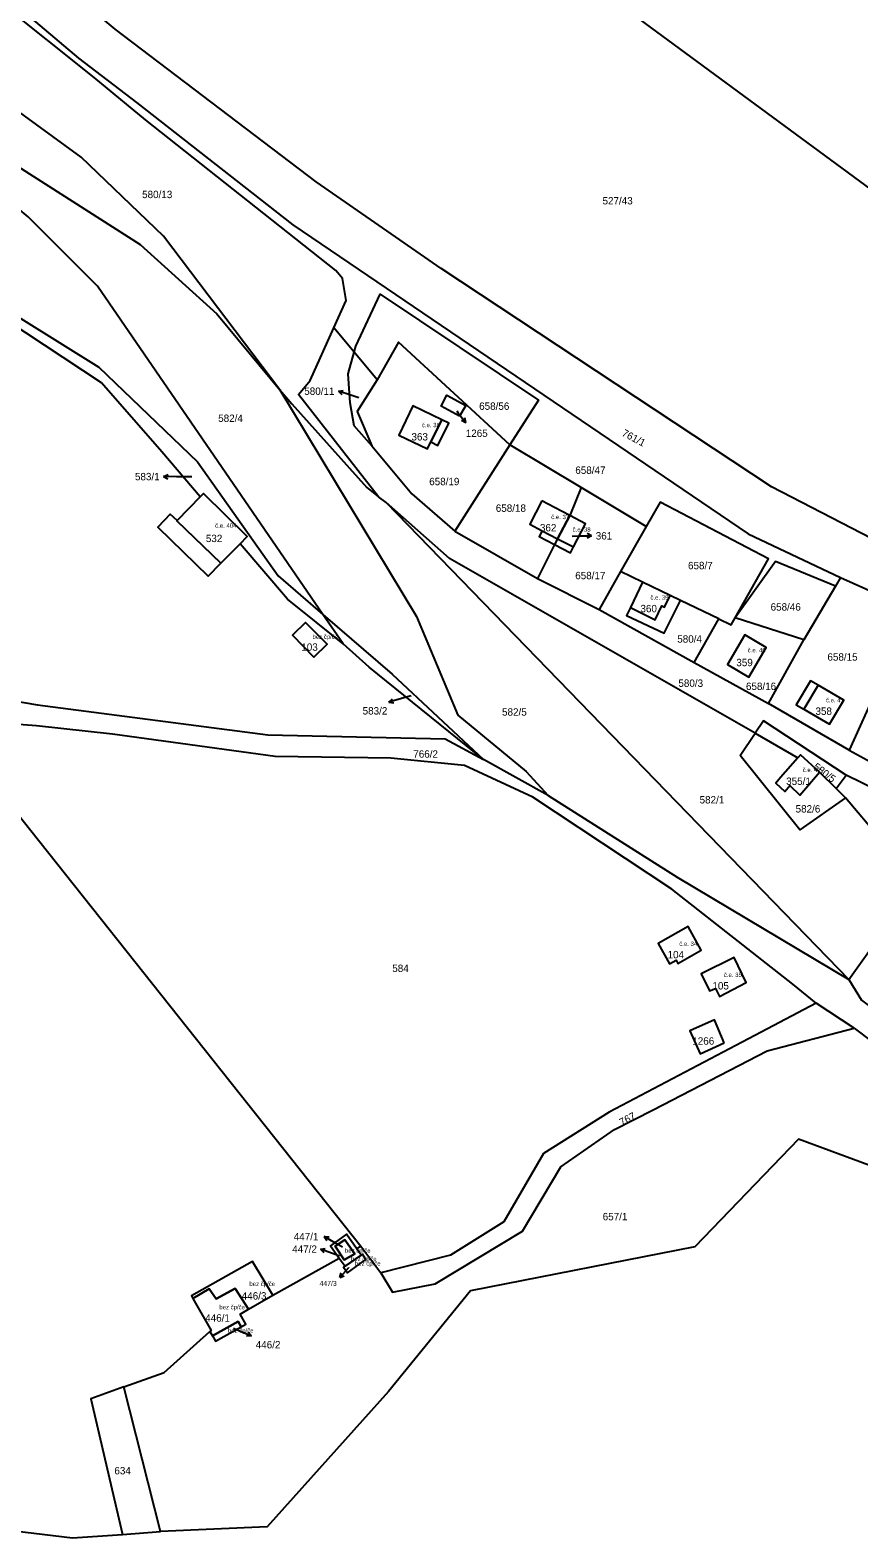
# Model space of a CAD drawing. Extents: x -887272 to -880188, y -1026687 to -1021896.
# Drawn here: x -884099.9 to -883908.9, y -1024224.8 to -1023877.6 of the extents above; entities that cross this region are included whole.
import ezdxf

# ---------------------------------------------------------------- set-up
doc = ezdxf.new("R2010")
doc.units = 0
for name, color, linetype in [('Definiční body', 7, 'Continuous'), ('Hranice parcel', 7, 'Continuous'), ('Parcelní čísla', 7, 'Continuous'), ('Polygon budovy', 7, 'Continuous'), ('Pop  PČ popisy', 7, 'Continuous'), ('Vnitřní kresba', 7, 'Continuous')]:
    doc.layers.add(name, color=color, linetype=linetype)

msp = doc.modelspace()

# ---------------------------------------------------------------- linework, layer by layer
at = {"layer": 'Hranice parcel'}
for p, q in [((-884025.18, -1023951.76), (-884029.85, -1023946.15)), ((-884019.89, -1023958.13), (-884025.18, -1023951.76)), ((-884042.31, -1023960.46), (-884039.58, -1023963.62)), ((-884011.69, -1023964.11), (-884014.91, -1023970.83)), ((-883989.29, -1023973.09), (-884001.97, -1023992.99)), ((-883972.86, -1023982.93), (-883989.29, -1023973.09)), ((-883972.86, -1023982.93), (-883975.49, -1023989.4)), ((-883957.89, -1023991.9), (-883972.86, -1023982.93)), ((-884017.85, -1023986.37), (-884019.55, -1023985.04)), ((-884017.85, -1023986.37), (-883911.25, -1024096.23)), ((-884001.97, -1023992.99), (-883982.95, -1024003.91)), ((-883957.89, -1023991.9), (-883963.8, -1024002.3)), ((-883979, -1023996.03), (-883982.95, -1024003.91)), ((-883982.95, -1024003.91), (-883968.75, -1024010.99)), ((-883963.8, -1024002.3), (-883968.75, -1024010.99)), ((-883958.76, -1024004.73), (-883963.8, -1024002.3)), ((-883913.13, -1024003.65), (-883914.3, -1024005.63)), ((-883914.3, -1024005.63), (-883921.56, -1024018.02)), ((-883941.19, -1024013.18), (-883949.97, -1024008.96)), ((-884027.71, -1024018.94), (-884032.38, -1024012.15)), ((-883968.75, -1024010.99), (-883946.83, -1024023.21)), ((-883946.83, -1024023.21), (-883941.19, -1024013.18)), ((-883921.56, -1024018.02), (-883937.39, -1024012.91)), ((-883929.72, -1024032.63), (-883921.56, -1024018.02)), ((-883946.83, -1024023.21), (-883929.72, -1024032.63)), ((-883904.58, -1024028.99), (-883911.13, -1024043.4)), ((-883911.13, -1024043.4), (-883929.72, -1024032.63)), ((-884120.19, -1024036.18), (-884023.67, -1024157.61)), ((-883936.29, -1024044.64), (-883932.83, -1024039.52)), ((-883932.83, -1024039.52), (-883922.95, -1024045.18)), ((-883980.51, -1024053.85), (-883995.38, -1024045.56)), ((-883911.13, -1024043.4), (-883899.81, -1024049.6)), ((-883917.94, -1024048.45), (-883914.16, -1024052.25)), ((-883914.16, -1024052.25), (-883911.85, -1024049.13)), ((-883898.73, -1024055.6), (-883911.85, -1024049.13)), ((-883912, -1024054.42), (-883914.16, -1024052.25)), ((-883980.51, -1024053.85), (-883950.8, -1024072.68)), ((-883904.07, -1024063.74), (-883912, -1024054.42)), ((-883950.8, -1024072.68), (-883911.25, -1024096.23)), ((-883911.25, -1024096.23), (-883895, -1024073.52)), ((-883909.98, -1024107.42), (-883918.72, -1024101.7)), ((-884027.29, -1024162.27), (-884023.6, -1024159.68)), ((-884024.65, -1024158.16), (-884023.67, -1024157.61)), ((-884023.6, -1024159.68), (-884024.65, -1024158.16)), ((-884023.67, -1024157.61), (-884019.06, -1024163.76)), ((-884043.9, -1024168.9), (-884028.63, -1024160.38)), ((-884028.63, -1024160.38), (-884027.29, -1024162.27)), ((-884049.54, -1024172.16), (-884043.9, -1024168.9)), ((-884058.46, -1024177.26), (-884057.87, -1024178.3)), ((-884069.78, -1024223.36), (-884078.26, -1024190.02)), ((-884078.6, -1024224), (-884069.78, -1024223.36))]:
    msp.add_line(p, q, dxfattribs=at)
for points in [[(-883756.5, -1024023.04), (-883767.66, -1024020.24), (-883797.06, -1024014.34), (-883842.62, -1024005.56), (-883874.8, -1024002.84), (-883906.02, -1023994.68), (-883929.04, -1023982.78), (-884005.12, -1023932.5), (-884033.98, -1023912.56), (-884080.28, -1023877.34), (-884136.58, -1023830.48), (-884162.3, -1023804.42), (-884180.14, -1023781.6), (-884204.86, -1023736.02), (-884224.62, -1023704.92), (-884247.24, -1023674.52), (-884253.66, -1023666.34), (-884254.22, -1023665.64)], [(-884128.87, -1023850.09), (-884088.74, -1023884.02), (-884075.38, -1023894.24), (-884039.32, -1023922.42), (-883934.44, -1023993.58), (-883913.13, -1024003.65)], [(-884042.31, -1023960.46), (-884069.15, -1023925.03), (-884088.08, -1023906.88), (-884124.51, -1023880.4), (-884129.67, -1023875.3), (-884133.64, -1023867.29), (-884134.98, -1023857.41), (-884133.42, -1023855.44), (-884132.27, -1023853.18), (-884130.36, -1023851.44)], [(-884029.85, -1023946.15), (-884027.02, -1023939.86), (-884027.86, -1023934.82), (-884029.41, -1023932.93), (-884073.28, -1023898.24), (-884085.07, -1023888.47), (-884106.9, -1023871.17), (-884122.73, -1023858.32), (-884130.36, -1023851.44)], [(-883979.65, -1023860.19), (-883882, -1023932), (-883653, -1023925)], [(-884134.64, -1023892.14), (-884120.26, -1023897.78), (-884074.52, -1023926.94), (-884056.83, -1023942.92), (-884042.31, -1023960.46)], [(-884032.38, -1024012.15), (-884084.32, -1023936.55), (-884100.33, -1023920.58), (-884134.64, -1023892.14)], [(-884060.68, -1023985.09), (-884069.54, -1023974.7), (-884083.38, -1023958.84), (-884122.86, -1023932.78), (-884157.22, -1023909.6)], [(-884157.22, -1023909.6), (-884084, -1023955.24), (-884061.26, -1023976.98), (-884042.7, -1024003.23), (-884032.38, -1024012.15)], [(-884025.18, -1023951.76), (-884024.81, -1023950.4), (-884019.24, -1023938.38), (-883982.71, -1023962.83), (-883989.29, -1023973.09)], [(-884019.55, -1023985.04), (-884038.05, -1023961.5), (-884035.31, -1023958.31), (-884029.85, -1023946.15)], [(-884021.14, -1023973.35), (-884025.21, -1023968.69), (-884026.08, -1023963.45), (-884026.55, -1023956.74), (-884025.18, -1023951.76)], [(-883989.29, -1023973.09), (-884014.99, -1023949.47), (-884019.89, -1023958.13)], [(-884019.89, -1023958.13), (-884024.5, -1023965.42), (-884021.14, -1023973.35)], [(-884042.31, -1023960.46), (-884010.85, -1024012.66), (-884001.27, -1024035.34), (-883985.6, -1024048.34), (-883980.51, -1024053.85)], [(-884000.92, -1023966.48), (-884005.13, -1023964.17), (-884003.82, -1023961.66), (-883999.45, -1023964.04), (-884000.92, -1023966.48)], [(-884039.58, -1023963.62), (-884022.28, -1023982.92), (-884019.55, -1023985.04)], [(-884014.91, -1023970.83), (-884008.33, -1023973.99), (-884007.55, -1023972.42), (-884005.95, -1023973.22), (-884003.4, -1023968.09), (-884005.02, -1023967.31), (-884011.69, -1023964.11)], [(-884021.14, -1023973.35), (-884011.88, -1023984.41), (-884001.97, -1023992.99)], [(-884060.68, -1023985.09), (-884065.94, -1023990.48), (-884067.55, -1023989.03), (-884070.44, -1023992.08), (-884058.82, -1024003.33), (-884055.91, -1024000.36), (-884051.49, -1023995.86)], [(-884051.49, -1023995.86), (-884049.83, -1023994.17), (-884059.91, -1023984.31), (-884060.68, -1023985.09)], [(-883932.83, -1024039.52), (-884003.19, -1023999.25), (-884017.85, -1023986.37)], [(-883981.99, -1023985.98), (-883984.7, -1023991.4), (-883981.87, -1023992.87)], [(-883975.49, -1023989.4), (-883979.06, -1023987.52), (-883981.99, -1023985.98)], [(-883937.39, -1024012.91), (-883929.74, -1023999.31), (-883954.68, -1023986.26), (-883957.89, -1023991.9)], [(-883975.49, -1023989.4), (-883978.31, -1023994.72), (-883979, -1023996.03)], [(-883979, -1023996.03), (-883975.36, -1023997.94), (-883974.68, -1023996.61), (-883971.93, -1023991.27), (-883975.49, -1023989.4)], [(-883981.87, -1023992.87), (-883982.55, -1023994.17), (-883979, -1023996.03)], [(-884027.71, -1024018.94), (-884040.58, -1024008.66), (-884051.49, -1023995.86)], [(-883914.3, -1024005.63), (-883928.14, -1023999.97), (-883937.39, -1024012.91)], [(-883913.13, -1024003.65), (-883904.38, -1024007.55), (-883899.62, -1024008.57)], [(-883958.76, -1024004.73), (-883961.55, -1024010.54), (-883962.46, -1024012.43), (-883953.74, -1024016.44), (-883949.97, -1024008.96)], [(-883949.97, -1024008.96), (-883952.36, -1024007.81), (-883958.76, -1024004.73)], [(-884039.41, -1024016.96), (-884034.45, -1024022), (-884031.43, -1024019.01), (-884036.38, -1024013.97), (-884039.41, -1024016.96)], [(-884032.38, -1024012.15), (-884016.42, -1024025.94), (-883995.38, -1024045.56)], [(-883941.19, -1024013.18), (-883938.35, -1024014.55), (-883937.39, -1024012.91)], [(-883935.21, -1024016.88), (-883939.2, -1024023.69), (-883934.27, -1024026.57), (-883930.29, -1024019.76), (-883935.21, -1024016.88)], [(-883995.38, -1024045.56), (-884021.72, -1024024.3), (-884027.71, -1024018.94)], [(-883918.3, -1024028.44), (-883920.05, -1024027.41), (-883923.36, -1024032.97), (-883921.6, -1024033.98), (-883915.64, -1024037.39), (-883912.38, -1024031.92), (-883918.3, -1024028.44)], [(-884123.06, -1024028.78), (-884098.18, -1024033), (-884045.1, -1024039.86), (-884004.26, -1024040.76), (-883995.38, -1024045.56)], [(-883918.72, -1024101.7), (-883924.14, -1024097.32), (-883952.02, -1024075.4), (-883984.02, -1024054.24), (-883999.74, -1024046.96), (-884016.72, -1024045.28), (-884043.42, -1024044.88), (-884080.84, -1024039.76), (-884098.38, -1024037.82), (-884120.19, -1024036.18)], [(-883911.85, -1024049.13), (-883930.9, -1024036.66), (-883932.83, -1024039.52)], [(-883912, -1024054.42), (-883922.51, -1024061.72), (-883936.29, -1024044.64)], [(-883922.95, -1024045.18), (-883926.93, -1024049.72), (-883928.07, -1024051.03), (-883925.94, -1024052.89), (-883924.8, -1024051.58), (-883922.51, -1024053.75), (-883917.94, -1024048.45)], [(-883917.94, -1024048.45), (-883922.36, -1024044.5), (-883922.95, -1024045.18)], [(-883945.27, -1024089.47), (-883948.2, -1024084.04), (-883955.18, -1024087.9), (-883952.57, -1024092.61), (-883951.04, -1024091.78), (-883950.61, -1024092.57), (-883945.27, -1024089.47)], [(-883941.94, -1024098.28), (-883941.02, -1024100.12), (-883934.9, -1024096.9), (-883937.64, -1024091.14), (-883945.24, -1024094.94), (-883943.34, -1024098.86), (-883941.94, -1024098.28)], [(-883911.25, -1024096.23), (-883908.31, -1024100.98), (-883902.86, -1024105.05)], [(-883918.72, -1024101.7), (-883931.44, -1024108.36), (-883966.42, -1024126.78), (-883981.56, -1024136.28), (-883990.7, -1024152.04), (-884002.96, -1024159.72), (-884019.06, -1024163.76)], [(-884019.06, -1024163.76), (-884016.34, -1024168.22), (-884006.56, -1024166.28), (-883986.4, -1024154.2), (-883977.56, -1024139.36), (-883965.2, -1024130.78), (-883956.28, -1024126.24), (-883930.04, -1024112.68), (-883909.98, -1024107.42)], [(-883939.92, -1024110.82), (-883942.16, -1024105.54), (-883947.82, -1024108.04), (-883945.46, -1024113.34), (-883939.92, -1024110.82)], [(-883909.98, -1024107.42), (-883905.62, -1024110.7), (-883897.3, -1024115.95)], [(-883855.91, -1024158.43), (-883859.24, -1024156.52), (-883860.34, -1024160.64), (-883875.1, -1024156.8), (-883873.62, -1024151.2), (-883922.82, -1024133), (-883946.68, -1024157.76), (-883998.42, -1024167.88), (-884017.26, -1024191.06), (-884045.27, -1024222.29), (-884069.78, -1024223.36)], [(-884024.65, -1024158.16), (-884026.93, -1024154.88), (-884030.62, -1024157.55), (-884028.63, -1024160.38)], [(-884027.36, -1024156.14), (-884029.58, -1024157.62), (-884027.48, -1024160.78), (-884025.04, -1024159.4), (-884027.36, -1024156.14)], [(-884027.29, -1024162.27), (-884027.62, -1024162.5), (-884026.74, -1024163.8), (-884022.48, -1024160.71), (-884023.31, -1024159.48), (-884023.6, -1024159.68)], [(-884263.42, -1024162.52), (-884211.46, -1024160.89), (-884176.88, -1024188.36), (-884125.84, -1024220.46), (-884090.08, -1024224.8), (-884078.6, -1024224)], [(-884043.9, -1024168.9), (-884048.59, -1024161.14), (-884062.67, -1024169.09), (-884062.34, -1024169.66)], [(-884049.54, -1024172.16), (-884052.64, -1024167.36), (-884057, -1024169.76), (-884058.6, -1024167.46), (-884062.34, -1024169.66)], [(-884062.34, -1024169.66), (-884058.11, -1024177.06), (-884058.46, -1024177.26)], [(-884051.21, -1024176.18), (-884050.18, -1024175.6), (-884051.46, -1024173.28), (-884049.54, -1024172.16)], [(-884078.26, -1024190.02), (-884069, -1024186.76), (-884058.46, -1024177.26)], [(-884057.87, -1024178.3), (-884051.94, -1024174.94), (-884051.21, -1024176.18)], [(-884057.87, -1024178.3), (-884057.14, -1024179.54), (-884051.21, -1024176.18)], [(-884078.26, -1024190.02), (-884085.9, -1024192.78), (-884078.6, -1024224)]]:
    msp.add_lwpolyline(points, dxfattribs=at)
at = {"layer": 'Polygon budovy'}
for points in [[(-884008.33, -1023973.99), (-884007.55, -1023972.42), (-884005.02, -1023967.31), (-884011.69, -1023964.11), (-884014.91, -1023970.83)], [(-884051.49, -1023995.86), (-884049.83, -1023994.17), (-884059.91, -1023984.31), (-884060.68, -1023985.09), (-884065.94, -1023990.48), (-884066.02, -1023990.57), (-884055.91, -1024000.36)], [(-883981.99, -1023985.98), (-883984.7, -1023991.4), (-883981.87, -1023992.87), (-883978.31, -1023994.72), (-883975.49, -1023989.4), (-883979.06, -1023987.52)], [(-883975.49, -1023989.4), (-883978.31, -1023994.72), (-883974.68, -1023996.61), (-883971.93, -1023991.27)], [(-883958.76, -1024004.73), (-883961.55, -1024010.54), (-883955.87, -1024013.38), (-883954.34, -1024010.18), (-883953.66, -1024010.51), (-883952.36, -1024007.81)], [(-884031.43, -1024019.01), (-884036.38, -1024013.97), (-884039.41, -1024016.96), (-884034.45, -1024022)], [(-883930.29, -1024019.76), (-883935.21, -1024016.88), (-883939.2, -1024023.69), (-883934.27, -1024026.57)], [(-883912.38, -1024031.92), (-883918.3, -1024028.44), (-883921.6, -1024033.98), (-883915.64, -1024037.39)], [(-883922.36, -1024044.5), (-883922.95, -1024045.18), (-883926.93, -1024049.72), (-883928.07, -1024051.03), (-883925.94, -1024052.89), (-883924.8, -1024051.58), (-883922.51, -1024053.75), (-883917.94, -1024048.45)], [(-883955.18, -1024087.9), (-883952.57, -1024092.61), (-883951.04, -1024091.78), (-883950.61, -1024092.57), (-883945.27, -1024089.47), (-883948.2, -1024084.04)], [(-883945.24, -1024094.94), (-883943.34, -1024098.86), (-883941.94, -1024098.28), (-883941.02, -1024100.12), (-883934.9, -1024096.9), (-883937.64, -1024091.14)], [(-884027.29, -1024162.27), (-884023.6, -1024159.68), (-884024.65, -1024158.16), (-884026.93, -1024154.88), (-884030.62, -1024157.55), (-884028.63, -1024160.38)], [(-884027.48, -1024160.78), (-884025.04, -1024159.4), (-884027.36, -1024156.14), (-884029.58, -1024157.62)], [(-884029.58, -1024157.62), (-884027.36, -1024156.14), (-884025.04, -1024159.4), (-884027.48, -1024160.78)], [(-884027.29, -1024162.27), (-884027.62, -1024162.5), (-884026.74, -1024163.8), (-884022.48, -1024160.71), (-884023.31, -1024159.48), (-884023.6, -1024159.68)], [(-884052.64, -1024167.36), (-884049.54, -1024172.16), (-884043.9, -1024168.9), (-884048.59, -1024161.14), (-884062.67, -1024169.09), (-884062.34, -1024169.66), (-884058.6, -1024167.46), (-884057, -1024169.76)], [(-884049.54, -1024172.16), (-884052.64, -1024167.36), (-884057, -1024169.76), (-884058.6, -1024167.46), (-884062.34, -1024169.66), (-884058.11, -1024177.06), (-884058.46, -1024177.26), (-884057.87, -1024178.3), (-884051.94, -1024174.94), (-884051.21, -1024176.18), (-884050.18, -1024175.6), (-884051.46, -1024173.28)], [(-884057.87, -1024178.3), (-884057.14, -1024179.54), (-884051.21, -1024176.18), (-884051.94, -1024174.94)]]:
    msp.add_lwpolyline(points, close=True, dxfattribs=at)
at = {"layer": 'Pop  PČ popisy'}
for p, q in [((-884028.84, -1023960.74), (-884027.74, -1023960.58)), ((-884025.99, -1023961.67), (-884028.84, -1023960.74)), ((-884028.84, -1023960.74), (-884028.05, -1023961.53)), ((-884024.1, -1023962.29), (-884025.99, -1023961.67)), ((-884001.51, -1023965.3), (-884001.28, -1023965.61)), ((-884001.28, -1023965.61), (-883999.47, -1023968.01)), ((-883999.47, -1023968.01), (-884000.48, -1023967.51)), ((-883999.47, -1023968.01), (-883999.68, -1023966.91)), ((-884069.09, -1023980.39), (-884068.08, -1023979.9)), ((-884066.09, -1023980.44), (-884069.09, -1023980.39)), ((-884069.09, -1023980.39), (-884068.1, -1023980.91)), ((-884062.57, -1023980.48), (-884066.09, -1023980.44)), ((-883970.53, -1023994.03), (-883971.54, -1023993.54)), ((-883974.99, -1023994.1), (-883973.53, -1023994.08)), ((-883973.53, -1023994.08), (-883970.53, -1023994.03)), ((-883970.53, -1023994.03), (-883971.52, -1023994.55)), ((-884014.28, -1024031.51), (-884017.17, -1024032.34)), ((-884017.17, -1024032.34), (-884016.34, -1024031.58)), ((-884012.07, -1024030.86), (-884014.28, -1024031.51)), ((-884017.17, -1024032.34), (-884016.06, -1024032.54)), ((-884029.49, -1024156.92), (-884032.09, -1024155.42)), ((-884032.09, -1024155.42), (-884030.97, -1024155.49)), ((-884032.09, -1024155.42), (-884031.47, -1024156.35)), ((-884032.98, -1024158.3), (-884031.87, -1024158.18)), ((-884030.16, -1024159.33), (-884032.98, -1024158.3)), ((-884032.98, -1024158.3), (-884032.21, -1024159.12)), ((-884028.59, -1024159.9), (-884030.16, -1024159.33)), ((-884027.89, -1024157.83), (-884029.49, -1024156.92)), ((-884026.5, -1024162.61), (-884028.51, -1024164.84)), ((-884026.47, -1024162.58), (-884026.5, -1024162.61)), ((-884028.51, -1024164.84), (-884028.21, -1024163.76)), ((-884028.51, -1024164.84), (-884027.47, -1024164.43)), ((-884053.03, -1024176.52), (-884051.62, -1024177.13)), ((-884051.62, -1024177.13), (-884048.86, -1024178.3)), ((-884048.86, -1024178.3), (-884049.58, -1024177.45)), ((-884048.86, -1024178.3), (-884049.97, -1024178.37))]:
    msp.add_line(p, q, dxfattribs=at)
at = {"layer": 'Vnitřní kresba'}
for p, q in [((-884005.02, -1023967.31), (-884007.55, -1023972.42)), ((-884065.94, -1023990.48), (-884066.02, -1023990.57)), ((-884055.91, -1024000.36), (-884066.02, -1023990.57)), ((-883981.87, -1023992.87), (-883978.31, -1023994.72)), ((-883978.31, -1023994.72), (-883974.68, -1023996.61)), ((-883961.55, -1024010.54), (-883955.87, -1024013.38)), ((-883955.87, -1024013.38), (-883954.34, -1024010.18)), ((-883954.34, -1024010.18), (-883953.66, -1024010.51)), ((-883953.66, -1024010.51), (-883952.36, -1024007.81)), ((-883918.3, -1024028.44), (-883921.6, -1024033.98))]:
    msp.add_line(p, q, dxfattribs=at)

# ---------------------------------------------------------------- texts
at = {"layer": 'Definiční body'}
for s, p in [('č.e. 36', (-884009.59, -1023969.03)), ('č.e. 37', (-883979.8, -1023990.2)), ('č.e. 404', (-884057.23, -1023992.19)), ('č.e. 38', (-883974.86, -1023993.09)), ('č.e. 39', (-883956.92, -1024008.75)), ('bez čp/če', (-884034.8, -1024017.78)), ('č.e. 40', (-883934.52, -1024020.88)), ('č.e. 41', (-883916.49, -1024032.39)), ('č.e. 42', (-883921.85, -1024048.45)), ('č.e. 34', (-883950.29, -1024088.49)), ('č.e. 35', (-883940.01, -1024095.63)), ('bez čp/če', (-884027.32, -1024159.15)), ('bez čp/če', (-884025.93, -1024161.05)), ('bez čp/če', (-884025.01, -1024162.11)), ('bez čp/če', (-884049.33, -1024166.81)), ('bez čp/če', (-884056.26, -1024172.17)), ('bez čp/če', (-884054.28, -1024177.56))]:
    msp.add_text(s, height=1, dxfattribs=at).set_placement(p)
at = {"layer": 'Parcelní čísla'}
for s, height, p in [('580/13', 1.7, (-884074.05, -1023916.28)), ('527/43', 1.7, (-883967.97, -1023917.73)), ('580/11', 1.7, (-884036.69, -1023961.59)), ('658/56', 1.7, (-883996.39, -1023965.03)), ('582/4', 1.7, (-884056.52, -1023967.82)), ('363', 1.7, (-884011.99, -1023972.09)), ('1265', 1.7, (-883999.48, -1023971.28)), ('583/1', 1.7, (-884075.7, -1023981.26)), ('658/47', 1.7, (-883974.24, -1023979.78)), ('658/19', 1.7, (-884007.9, -1023982.39)), ('658/18', 1.7, (-883992.56, -1023988.52)), ('362', 1.7, (-883982.39, -1023993.03)), ('361', 1.7, (-883969.53, -1023994.9)), ('532', 1.7, (-884059.36, -1023995.49)), ('658/7', 1.7, (-883948.27, -1024001.74)), ('658/17', 1.7, (-883974.26, -1024004.04)), ('360', 1.7, (-883959.23, -1024011.65)), ('658/46', 1.7, (-883929.24, -1024011.27)), ('580/4', 1.7, (-883950.75, -1024018.65)), ('103', 1.7, (-884037.37, -1024020.52)), ('658/15', 1.7, (-883916.15, -1024022.79)), ('359', 1.7, (-883937.14, -1024024.07)), ('580/3', 1.7, (-883950.49, -1024028.83)), ('658/16', 1.7, (-883934.92, -1024029.55)), ('583/2', 1.7, (-884023.24, -1024035.2)), ('582/5', 1.7, (-883991.12, -1024035.46)), ('358', 1.7, (-883918.9, -1024035.28)), ('766/2', 1.7, (-884011.57, -1024045.14)), ('355/1', 1.7, (-883925.66, -1024051.41)), ('582/1', 1.7, (-883945.6, -1024055.68)), ('582/6', 1.7, (-883923.48, -1024057.77)), ('104', 1.7, (-883952.98, -1024091.34)), ('584', 1.7, (-884016.41, -1024094.49)), ('105', 1.7, (-883942.65, -1024098.52)), ('1266', 1.7, (-883947.29, -1024111.23)), ('657/1', 1.7, (-883967.93, -1024151.67)), ('447/1', 1.7, (-884039.11, -1024156.28)), ('447/2', 1.7, (-884039.46, -1024159.15)), ('447/3', 1.14, (-884033.16, -1024166.77)), ('446/3', 1.7, (-884051.1, -1024169.93)), ('446/1', 1.7, (-884059.51, -1024175.01)), ('446/2', 1.7, (-884047.87, -1024181.17)), ('634', 1.7, (-884080.44, -1024210.18))]:
    msp.add_text(s, height=height, dxfattribs=at).set_placement(p)
for s, rotation, p in [('761/1', 332, (-883963.67, -1023970.9)), ('580/5', 323, (-883919.59, -1024047.56)), ('767', 28, (-883963.51, -1024129.97))]:
    msp.add_text(s, height=1.7, rotation=rotation, dxfattribs=at).set_placement(p)

doc.saveas('drawing.dxf')
